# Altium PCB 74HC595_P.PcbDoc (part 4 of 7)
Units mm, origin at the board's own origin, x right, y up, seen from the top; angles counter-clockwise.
Board outline 89.11 x 89.03 mm, 2 copper layers (Top Layer, Bottom Layer); 552 components, 23 nets, 1488 pads, 408 vias.
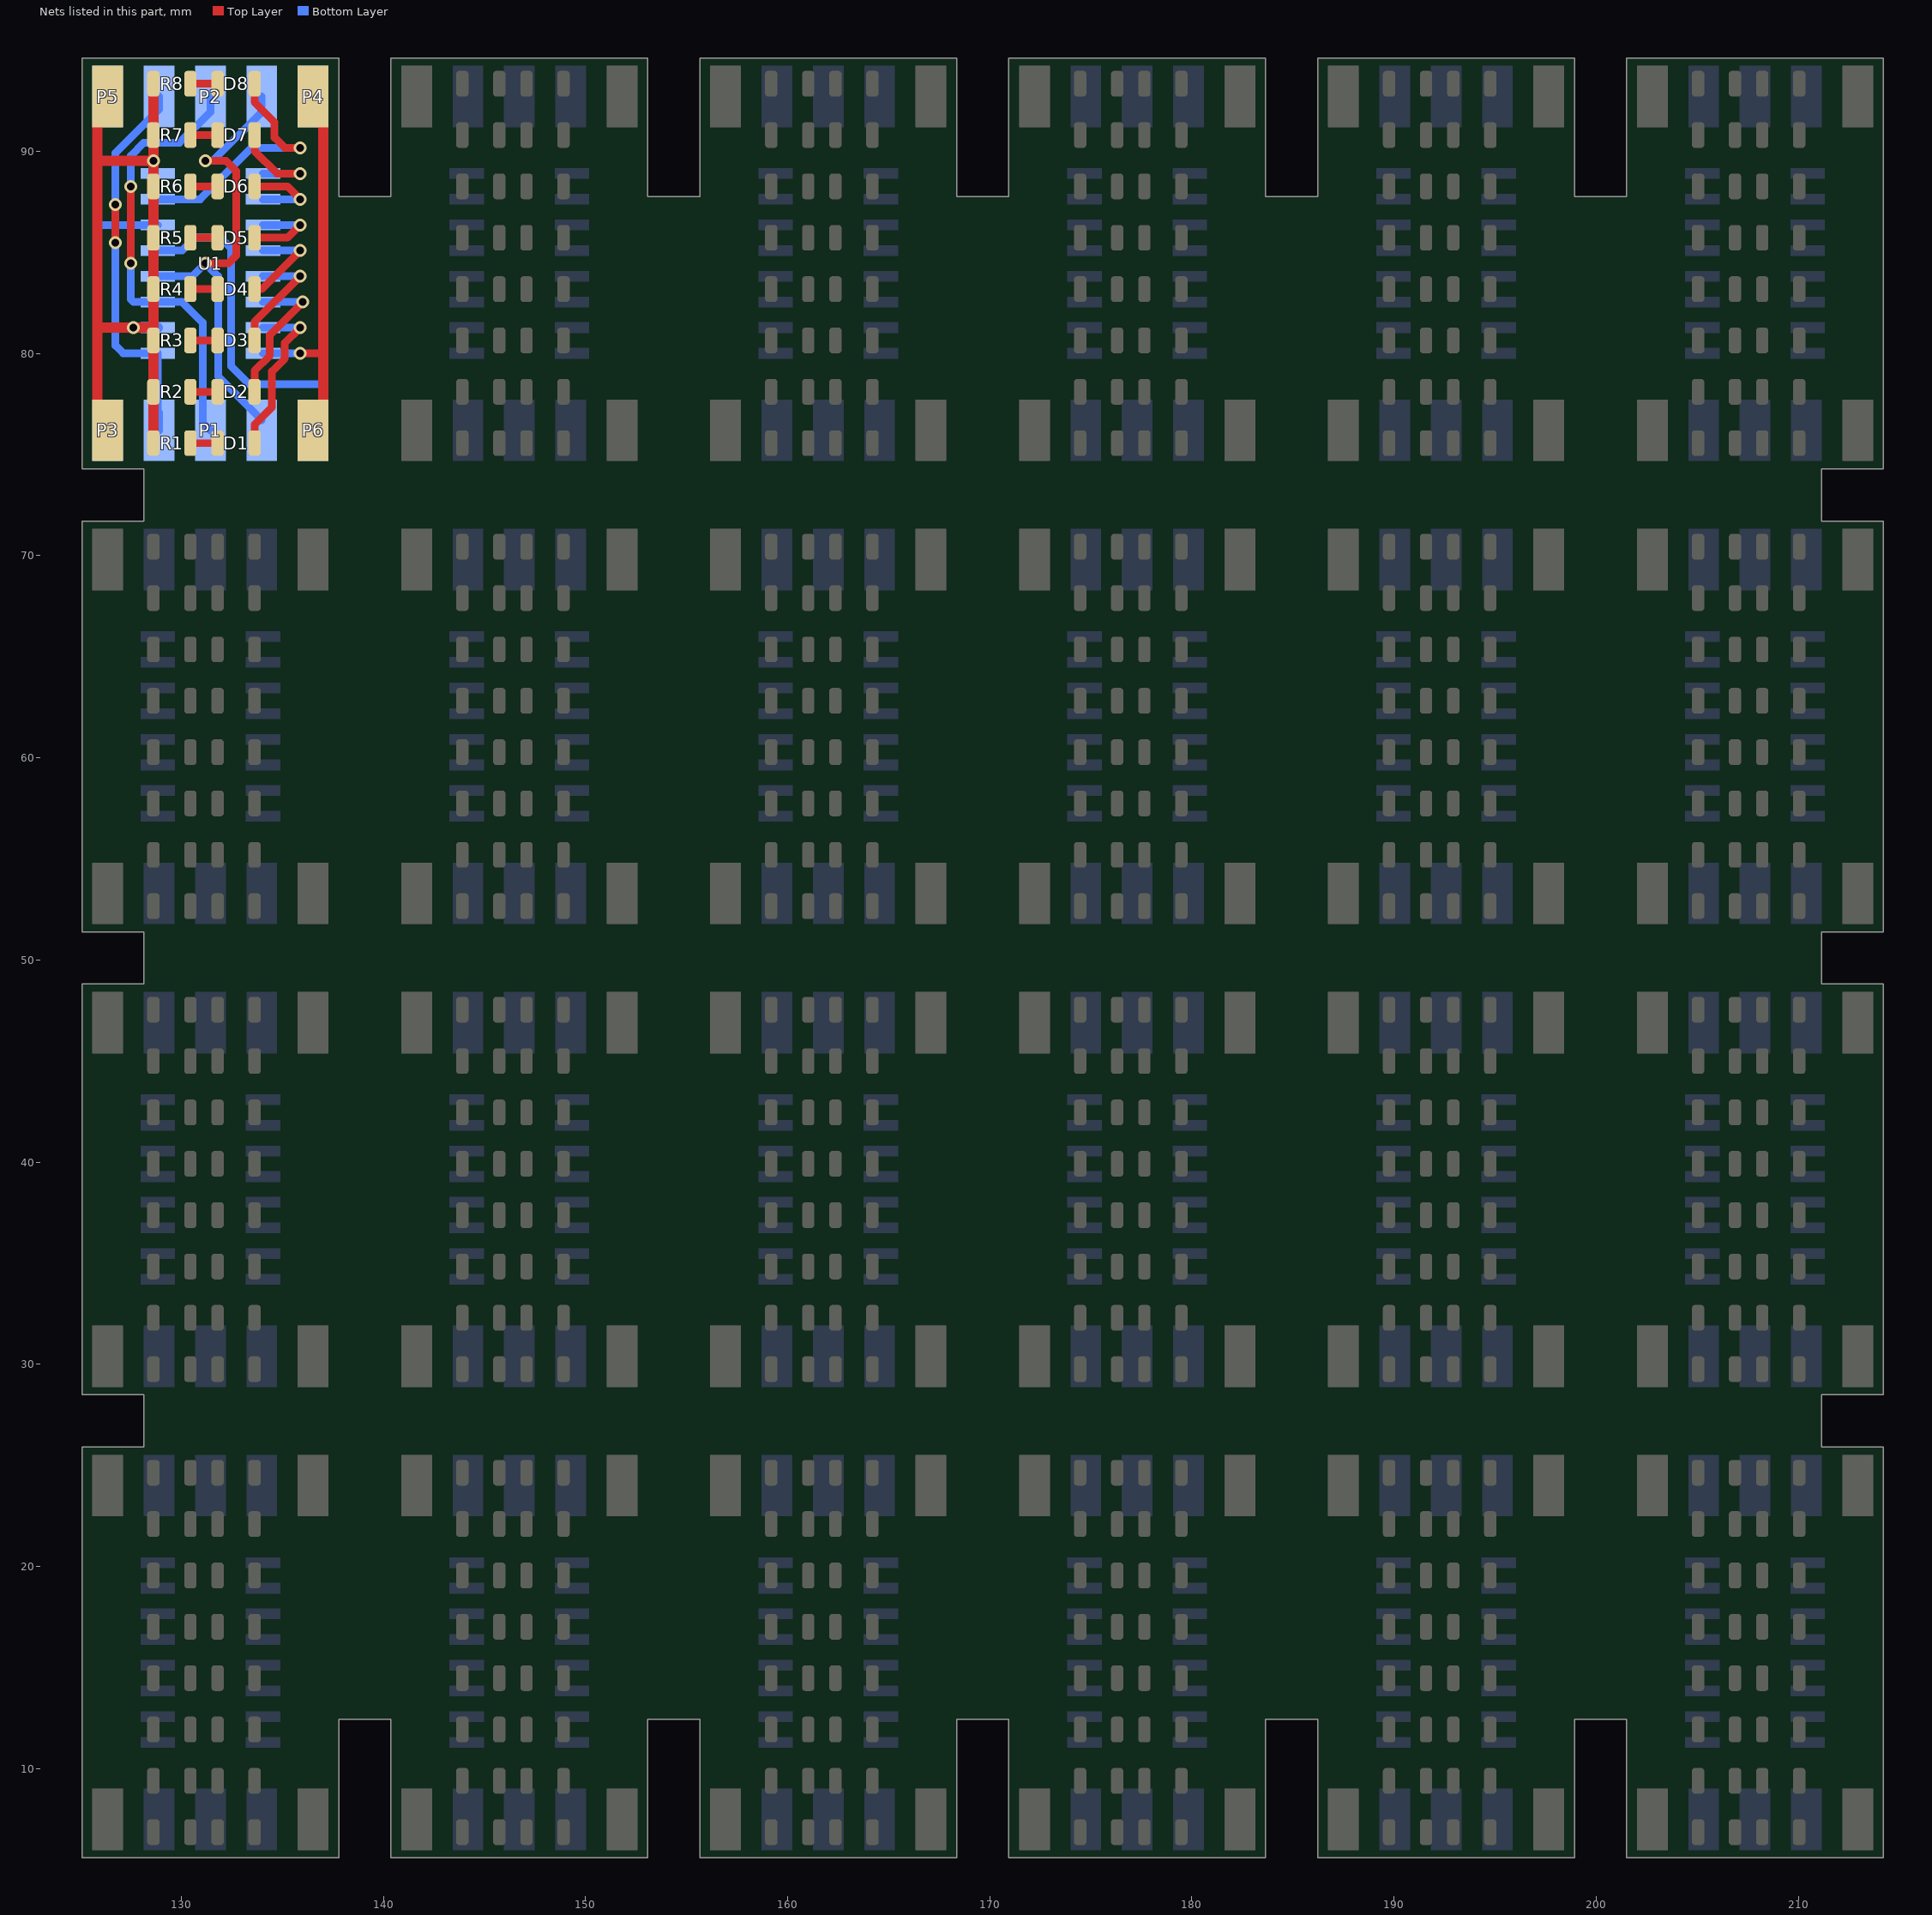
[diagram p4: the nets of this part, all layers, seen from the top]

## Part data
D1 D1_1 D1_1_1 D1_1_2 D1_1_3 D1_1_4 D1_2 D1_2_1 D1_2_1_1 D1_2_1_1_1 D1_2_1_1_2 D1_2_1_1_3 D1_2_1_1_4 D1_2_2 D1_2_2_1 D1_2_2_1_1 D1_2_2_1_2 D1_2_2_1_3 D1_2_2_1_4 D1_2_3 D1_2_3_1 D1_2_3_2 D1_2_3_3 D1_2_3_4 D2 D2_1 D2_1_1 D2_1_2 D2_1_3 D2_1_4 D2_2 D2_2_1 D2_2_1_1 D2_2_1_1_1 D2_2_1_1_2 D2_2_1_1_3 D2_2_1_1_4 D2_2_2 D2_2_2_1 D2_2_2_1_1 D2_2_2_1_2 D2_2_2_1_3 D2_2_2_1_4 D2_2_3 D2_2_3_1 D2_2_3_2 D2_2_3_3 D2_2_3_4 D3 D3_1 D3_1_1 D3_1_2 D3_1_3 D3_1_4 D3_2 D3_2_1 D3_2_1_1 D3_2_1_1_1 D3_2_1_1_2 D3_2_1_1_3 D3_2_1_1_4 D3_2_2 D3_2_2_1 D3_2_2_1_1 D3_2_2_1_2 D3_2_2_1_3 D3_2_2_1_4 D3_2_3 D3_2_3_1 D3_2_3_2 D3_2_3_3 D3_2_3_4 D4 D4_1 D4_1_1 D4_1_2 D4_1_3 D4_1_4 D4_2 D4_2_1 D4_2_1_1 D4_2_1_1_1 D4_2_1_1_2 D4_2_1_1_3 D4_2_1_1_4 D4_2_2 D4_2_2_1 D4_2_2_1_1 D4_2_2_1_2 D4_2_2_1_3 D4_2_2_1_4 D4_2_3 D4_2_3_1 D4_2_3_2 D4_2_3_3 D4_2_3_4 D5 D5_1 D5_1_1 D5_1_2 D5_1_3 D5_1_4 D5_2 D5_2_1 D5_2_1_1 D5_2_1_1_1 D5_2_1_1_2 D5_2_1_1_3 D5_2_1_1_4 D5_2_2 D5_2_2_1 D5_2_2_1_1 D5_2_2_1_2 D5_2_2_1_3 D5_2_2_1_4 D5_2_3 D5_2_3_1 D5_2_3_2 D5_2_3_3 D5_2_3_4 D6 D6_1 D6_1_1 D6_1_2 D6_1_3 D6_1_4 D6_2 D6_2_1 D6_2_1_1 D6_2_1_1_1 D6_2_1_1_2 D6_2_1_1_3 D6_2_1_1_4 D6_2_2 D6_2_2_1 D6_2_2_1_1 D6_2_2_1_2 D6_2_2_1_3 D6_2_2_1_4 D6_2_3 D6_2_3_1 D6_2_3_2 D6_2_3_3 D6_2_3_4 D7 D7_1 D7_1_1 D7_1_2 D7_1_3 D7_1_4 D7_2 D7_2_1 D7_2_1_1 D7_2_1_1_1 D7_2_1_1_2 D7_2_1_1_3 D7_2_1_1_4 D7_2_2 D7_2_2_1 D7_2_2_1_1 D7_2_2_1_2 D7_2_2_1_3 D7_2_2_1_4 D7_2_3 D7_2_3_1 D7_2_3_2 D7_2_3_3 D7_2_3_4 D8 D8_1 D8_1_1 D8_1_2 D8_1_3 D8_1_4 D8_2 D8_2_1 D8_2_1_1 D8_2_1_1_1 D8_2_1_1_2 D8_2_1_1_3 D8_2_1_1_4 D8_2_2 D8_2_2_1 D8_2_2_1_1 D8_2_2_1_2 D8_2_2_1_3 D8_2_2_1_4 D8_2_3 D8_2_3_1 D8_2_3_2 D8_2_3_3 D8_2_3_4: library part LED_0805, "LED"
P1 P1_1 P1_1_1 P1_1_2 P1_1_3 P1_1_4 P1_2 P1_2_1 P1_2_1_1 P1_2_1_1_1 P1_2_1_1_2 P1_2_1_1_3 P1_2_1_1_4 P1_2_2 P1_2_2_1 P1_2_2_1_1 P1_2_2_1_2 P1_2_2_1_3 P1_2_2_1_4 P1_2_3 P1_2_3_1 P1_2_3_2 P1_2_3_3 P1_2_3_4 P2 P2_1 P2_1_1 P2_1_2 P2_1_3 P2_1_4 P2_2 P2_2_1 P2_2_1_1 P2_2_1_1_1 P2_2_1_1_2 P2_2_1_1_3 P2_2_1_1_4 P2_2_2 P2_2_2_1 P2_2_2_1_1 P2_2_2_1_2 P2_2_2_1_3 P2_2_2_1_4 P2_2_3 P2_2_3_1 P2_2_3_2 P2_2_3_3 P2_2_3_4: "Header, 5-Pin"
P3 P3_1 P3_1_1 P3_1_2 P3_1_3 P3_1_4 P3_2 P3_2_1 P3_2_1_1 P3_2_1_1_1 P3_2_1_1_2 P3_2_1_1_3 P3_2_1_1_4 P3_2_2 P3_2_2_1 P3_2_2_1_1 P3_2_2_1_2 P3_2_2_1_3 P3_2_2_1_4 P3_2_3 P3_2_3_1 P3_2_3_2 P3_2_3_3 P3_2_3_4 P4 P4_1 P4_1_1 P4_1_2 P4_1_3 P4_1_4 P4_2 P4_2_1 P4_2_1_1 P4_2_1_1_1 P4_2_1_1_2 P4_2_1_1_3 P4_2_1_1_4 P4_2_2 P4_2_2_1 P4_2_2_1_1 P4_2_2_1_2 P4_2_2_1_3 P4_2_2_1_4 P4_2_3 P4_2_3_1 P4_2_3_2 P4_2_3_3 P4_2_3_4 P5 P5_1 P5_1_1 P5_1_2 P5_1_3 P5_1_4 P5_2 P5_2_1 P5_2_1_1 P5_2_1_1_1 P5_2_1_1_2 P5_2_1_1_3 P5_2_1_1_4 P5_2_2 P5_2_2_1 P5_2_2_1_1 P5_2_2_1_2 P5_2_2_1_3 P5_2_2_1_4 P5_2_3 P5_2_3_1 P5_2_3_2 P5_2_3_3 P5_2_3_4 P6 P6_1 P6_1_1 P6_1_2 P6_1_3 P6_1_4 P6_2 P6_2_1 P6_2_1_1 P6_2_1_1_1 P6_2_1_1_2 P6_2_1_1_3 P6_2_1_1_4 P6_2_2 P6_2_2_1 P6_2_2_1_1 P6_2_2_1_2 P6_2_2_1_3 P6_2_2_1_4 P6_2_3 P6_2_3_1 P6_2_3_2 P6_2_3_3 P6_2_3_4: "Header, 1-Pin"
R1 R1_1 R1_1_1 R1_1_2 R1_1_3 R1_1_4 R1_2 R1_2_1 R1_2_1_1 R1_2_1_1_1 R1_2_1_1_2 R1_2_1_1_3 R1_2_1_1_4 R1_2_2 R1_2_2_1 R1_2_2_1_1 R1_2_2_1_2 R1_2_2_1_3 R1_2_2_1_4 R1_2_3 R1_2_3_1 R1_2_3_2 R1_2_3_3 R1_2_3_4 R2 R2_1 R2_1_1 R2_1_2 R2_1_3 R2_1_4 R2_2 R2_2_1 R2_2_1_1 R2_2_1_1_1 R2_2_1_1_2 R2_2_1_1_3 R2_2_1_1_4 R2_2_2 R2_2_2_1 R2_2_2_1_1 R2_2_2_1_2 R2_2_2_1_3 R2_2_2_1_4 R2_2_3 R2_2_3_1 R2_2_3_2 R2_2_3_3 R2_2_3_4 R3 R3_1 R3_1_1 R3_1_2 R3_1_3 R3_1_4 R3_2 R3_2_1 R3_2_1_1 R3_2_1_1_1 R3_2_1_1_2 R3_2_1_1_3 R3_2_1_1_4 R3_2_2 R3_2_2_1 R3_2_2_1_1 R3_2_2_1_2 R3_2_2_1_3 R3_2_2_1_4 R3_2_3 R3_2_3_1 R3_2_3_2 R3_2_3_3 R3_2_3_4 R4 R4_1 R4_1_1 R4_1_2 R4_1_3 R4_1_4 R4_2 R4_2_1 R4_2_1_1 R4_2_1_1_1 R4_2_1_1_2 R4_2_1_1_3 R4_2_1_1_4 R4_2_2 R4_2_2_1 R4_2_2_1_1 R4_2_2_1_2 R4_2_2_1_3 R4_2_2_1_4 R4_2_3 R4_2_3_1 R4_2_3_2 R4_2_3_3 R4_2_3_4 R5 R5_1 R5_1_1 R5_1_2 R5_1_3 R5_1_4 R5_2 R5_2_1 R5_2_1_1 R5_2_1_1_1 R5_2_1_1_2 R5_2_1_1_3 R5_2_1_1_4 R5_2_2 R5_2_2_1 R5_2_2_1_1 R5_2_2_1_2 R5_2_2_1_3 R5_2_2_1_4 R5_2_3 R5_2_3_1 R5_2_3_2 R5_2_3_3 R5_2_3_4 R6 R6_1 R6_1_1 R6_1_2 R6_1_3 R6_1_4 R6_2 R6_2_1 R6_2_1_1 R6_2_1_1_1 R6_2_1_1_2 R6_2_1_1_3 R6_2_1_1_4 R6_2_2 R6_2_2_1 R6_2_2_1_1 R6_2_2_1_2 R6_2_2_1_3 R6_2_2_1_4 R6_2_3 R6_2_3_1 R6_2_3_2 R6_2_3_3 R6_2_3_4 R7 R7_1 R7_1_1 R7_1_2 R7_1_3 R7_1_4 R7_2 R7_2_1 R7_2_1_1 R7_2_1_1_1 R7_2_1_1_2 R7_2_1_1_3 R7_2_1_1_4 R7_2_2 R7_2_2_1 R7_2_2_1_1 R7_2_2_1_2 R7_2_2_1_3 R7_2_2_1_4 R7_2_3 R7_2_3_1 R7_2_3_2 R7_2_3_3 R7_2_3_4 R8 R8_1 R8_1_1 R8_1_2 R8_1_3 R8_1_4 R8_2 R8_2_1 R8_2_1_1 R8_2_1_1_1 R8_2_1_1_2 R8_2_1_1_3 R8_2_1_1_4 R8_2_2 R8_2_2_1 R8_2_2_1_1 R8_2_2_1_2 R8_2_2_1_3 R8_2_2_1_4 R8_2_3 R8_2_3_1 R8_2_3_2 R8_2_3_3 R8_2_3_4: library part Res_0805, "Resistor"
U1 U1_1 U1_1_1 U1_1_2 U1_1_3 U1_1_4 U1_2 U1_2_1 U1_2_1_1 U1_2_1_1_1 U1_2_1_1_2 U1_2_1_1_3 U1_2_1_1_4 U1_2_2 U1_2_2_1 U1_2_2_1_1 U1_2_2_1_2 U1_2_2_1_3 U1_2_2_1_4 U1_2_3 U1_2_3_1 U1_2_3_2 U1_2_3_3 U1_2_3_4: "No Description Available"

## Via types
v1: diameter 0.635, hole 0.381, Top Layer to Bottom Layer, 408 vias

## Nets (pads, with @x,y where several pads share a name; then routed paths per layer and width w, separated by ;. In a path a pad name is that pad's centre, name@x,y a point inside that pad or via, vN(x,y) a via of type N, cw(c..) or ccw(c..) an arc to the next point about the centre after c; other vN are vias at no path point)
BITOUT: P1.2 P2.2 U1.9 | length 20.1
  Top Layer w0.381: v1(126.746,85.471) v1(126.746,87.376)
  Bottom Layer w0.381: v1(126.746,85.471) 126.746,80.391 127.127,80.01 U1.9@128.841,80.01 P1.2@128.841,76.263 ; v1(126.746,87.376) 126.746,89.916 128.905,92.075 P2.2@128.905,92.71 ; P1.2@128.905,76.2 P1.2@128.905,77.089
BITSCLK: P1.3 P2.3 U1.11 | length 22.2
  Top Layer w0.381: v1(127.508,84.455) v1(127.508,88.265)
  Bottom Layer w0.381: v1(127.508,84.455) 127.508,82.677 127.635,82.55 U1.11@128.841,82.55 130.048,82.55 131.064,81.534 131.064,76.581 P1.3@131.445,76.2 ; v1(127.508,88.265) 127.508,89.78 128.152,90.424 129.921,90.424 131.445,91.948 P2.3@131.445,92.71
DATAINPUT: P1.1 P2.1 U1.14 | length 18.1
  Bottom Layer w0.381: P1.1@125.857,76.835 P2.1@125.857,92.075 ; 125.984,86.36 U1.14@128.841,86.36
GND: P4.1 P6.1 U1.8 | length 17
  Top Layer w0.381: v1(135.89,80.01) 137.033,80.01
  Top Layer w0.508: P6.1@137.033,77.47 137.033,80.01 P4.1@137.033,91.44
  Bottom Layer w0.381: U1.8@134.048,80.01 v1(135.89,80.01)
MEMSCLK: P1.4 P2.4 U1.12 | length 23.7
  Top Layer w0.381: v1(131.191,84.455) 132.334,84.455 132.715,84.836 132.715,89.027 132.207,89.535 v1(131.191,89.535)
  Bottom Layer w0.381: U1.12@128.841,83.82 130.556,83.82 v1(131.191,84.455) 131.826,83.82 131.826,78.867 P1.4@133.985,76.708 ; v1(131.191,89.535) 131.572,89.535 133.985,91.948 P2.4@133.985,92.71
NetD1_2: D1.2 R1.1 | length 1.3
  Top Layer w0.381: R1.1@130.454,75.565 D1.2@131.801,75.565
NetD2_2: D2.2 R2.1 | length 1.3
  Top Layer w0.381: R2.1@130.454,78.105 D2.2@131.801,78.105
NetD3_2: D3.2 R3.1 | length 1.3
  Top Layer w0.381: R3.1@130.454,80.645 D3.2@131.801,80.645
NetD4_2: D4.2 R4.1 | length 1.3
  Top Layer w0.381: R4.1@130.454,83.185 D4.2@131.801,83.185
NetD5_2: D5.2 R5.1 | length 1.3
  Top Layer w0.381: R5.1@130.454,85.725 D5.2@131.801,85.725
NetD6_2: D6.2 R6.1 | length 1.3
  Top Layer w0.381: R6.1@130.454,88.265 D6.2@131.801,88.265
NetD7_2: D7.2 R7.1 | length 1.3
  Top Layer w0.381: R7.1@130.454,90.805 D7.2@131.801,90.805
NetD8_2: D8.2 R8.1 | length 1.3
  Top Layer w0.381: R8.1@130.454,93.345 D8.2@131.801,93.345
OUTENABLE: P1.5 P2.5 U1.13 | length 30.1
  Bottom Layer w0.381: U1.13@128.841,85.09 130.048,85.09 130.683,85.725 131.953,85.725 132.461,85.217 132.461,79.375 133.35,78.486 137.033,78.486 ; P1.5@137.033,76.835 137.033,78.486 ; P2.5@137.033,92.075 137.033,78.486
Q0: D8.1 U1.15 | length 12.7
  Top Layer w0.381: D8.1@133.629,93.345 133.629,92.431 134.62,91.44 134.62,90.678 135.128,90.17 v1(135.89,90.17)
  Bottom Layer w0.381: U1.15@128.841,87.63 130.937,87.63 133.477,90.17 v1(135.89,90.17)
Q1: D7.1 U1.1 | length 5.6
  Top Layer w0.381: D7.1@133.629,90.591 D7.1@133.629,90.805 133.629,90.018 134.747,88.9 v1(135.89,88.9)
  Bottom Layer w0.381: U1.1@134.048,88.9 v1(135.89,88.9)
Q2: D6.1 U1.2 | length 4.4
  Top Layer w0.381: D6.1@133.629,88.265 135.255,88.265 v1(135.89,87.63)
  Bottom Layer w0.381: U1.2@134.048,87.63 v1(135.89,87.63)
Q3: D5.1 U1.3 | length 4.4
  Top Layer w0.381: D5.1@133.629,85.725 135.255,85.725 v1(135.89,86.36)
  Bottom Layer w0.381: U1.3@134.048,86.36 v1(135.89,86.36)
Q4: D4.1 U1.4 | length 5.2
  Top Layer w0.381: D4.1@133.629,83.464 D4.1@133.629,83.185 133.985,83.185 v1(135.89,85.09)
  Bottom Layer w0.381: U1.4@134.048,85.09 v1(135.89,85.09)
Q5: D3.1 U1.5 | length 6
  Top Layer w0.381: D3.1@133.629,80.645 133.629,81.559 v1(135.89,83.82)
  Bottom Layer w0.381: U1.5@134.048,83.82 v1(135.89,83.82)
Q6: D2.1 U1.6 | length 7.4
  Top Layer w0.381: D2.1@133.629,78.105 133.629,79.146 134.379,79.896 134.379,80.912 v1(136.017,82.55)
  Bottom Layer w0.381: U1.6@134.048,82.55 v1(136.017,82.55)
Q7: D1.1 U1.7 | length 8.5
  Top Layer w0.381: D1.1@133.629,75.565 133.629,76.479 134.493,77.343 134.493,79.112 135.128,79.747 135.128,80.518 v1(135.89,81.28)
  Bottom Layer w0.381: U1.7@134.048,81.28 v1(135.89,81.28)
VCC: P3.1 P5.1 R1.2 R2.2 R3.2 R4.2 R5.2 R6.2 R7.2 R8.2 U1.10 U1.16 | length 38.7
  Top Layer w0.508: P3.1@125.857,77.47 P5.1@125.857,91.44 ; 125.984,81.28 v1(127.635,81.28) 128.626,81.28 ; 125.984,89.535 v1(128.626,89.535) ; R1.2@128.626,75.565 R2.2@128.626,78.105 R3.2@128.626,80.645 R4.2@128.626,83.185 R5.2@128.626,85.725 R6.2@128.626,88.265 v1(128.626,89.535) ; R8.2@128.626,93.345 R7.2@128.626,90.805 v1(128.626,89.535)
  Bottom Layer w0.508: v1(127.635,81.28) U1.10@128.841,81.28 ; U1.16@128.626,89.116 v1(128.626,89.535)
pads on no net: D1_1.1 D1_1.2 D1_1_1.1 D1_1_1.2 D1_1_2.1 D1_1_2.2 D1_1_3.1 D1_1_3.2 D1_1_4.1 D1_1_4.2 D1_2.1 D1_2.2 D1_2_1.1 D1_2_1.2 D1_2_1_1.1 D1_2_1_1.2 D1_2_1_1_1.1 D1_2_1_1_1.2 D1_2_1_1_2.1 D1_2_1_1_2.2 D1_2_1_1_3.1 D1_2_1_1_3.2 D1_2_1_1_4.1 D1_2_1_1_4.2 D1_2_2.1 D1_2_2.2 D1_2_2_1.1 D1_2_2_1.2 D1_2_2_1_1.1 D1_2_2_1_1.2 D1_2_2_1_2.1 D1_2_2_1_2.2 D1_2_2_1_3.1 D1_2_2_1_3.2 D1_2_2_1_4.1 D1_2_2_1_4.2 D1_2_3.1 D1_2_3.2 D1_2_3_1.1 D1_2_3_1.2 D1_2_3_2.1 D1_2_3_2.2 D1_2_3_3.1 D1_2_3_3.2 D1_2_3_4.1 D1_2_3_4.2 D2_1.1 D2_1.2 D2_1_1.1 D2_1_1.2 D2_1_2.1 D2_1_2.2 D2_1_3.1 D2_1_3.2 D2_1_4.1 D2_1_4.2 D2_2.1 D2_2.2 D2_2_1.1 D2_2_1.2 D2_2_1_1.1 D2_2_1_1.2 D2_2_1_1_1.1 D2_2_1_1_1.2 D2_2_1_1_2.1 D2_2_1_1_2.2 D2_2_1_1_3.1 D2_2_1_1_3.2 D2_2_1_1_4.1 D2_2_1_1_4.2 D2_2_2.1 D2_2_2.2 D2_2_2_1.1 D2_2_2_1.2 D2_2_2_1_1.1 D2_2_2_1_1.2 D2_2_2_1_2.1 D2_2_2_1_2.2 D2_2_2_1_3.1 D2_2_2_1_3.2 D2_2_2_1_4.1 D2_2_2_1_4.2 D2_2_3.1 D2_2_3.2 D2_2_3_1.1 D2_2_3_1.2 D2_2_3_2.1 D2_2_3_2.2 D2_2_3_3.1 D2_2_3_3.2 D2_2_3_4.1 D2_2_3_4.2 D3_1.1 D3_1.2 D3_1_1.1 D3_1_1.2 D3_1_2.1 D3_1_2.2 D3_1_3.1 D3_1_3.2 D3_1_4.1 D3_1_4.2 D3_2.1 D3_2.2 D3_2_1.1 D3_2_1.2 D3_2_1_1.1 D3_2_1_1.2 D3_2_1_1_1.1 D3_2_1_1_1.2 D3_2_1_1_2.1 D3_2_1_1_2.2 D3_2_1_1_3.1 D3_2_1_1_3.2 D3_2_1_1_4.1 D3_2_1_1_4.2 D3_2_2.1 D3_2_2.2 D3_2_2_1.1 D3_2_2_1.2 D3_2_2_1_1.1 D3_2_2_1_1.2 D3_2_2_1_2.1 D3_2_2_1_2.2 D3_2_2_1_3.1 D3_2_2_1_3.2 D3_2_2_1_4.1 D3_2_2_1_4.2 D3_2_3.1 D3_2_3.2 D3_2_3_1.1 D3_2_3_1.2 D3_2_3_2.1 D3_2_3_2.2 D3_2_3_3.1 D3_2_3_3.2 D3_2_3_4.1 D3_2_3_4.2 D4_1.1 D4_1.2 D4_1_1.1 D4_1_1.2 D4_1_2.1 D4_1_2.2 D4_1_3.1 D4_1_3.2 D4_1_4.1 D4_1_4.2 D4_2.1 D4_2.2 D4_2_1.1 D4_2_1.2 D4_2_1_1.1 D4_2_1_1.2 D4_2_1_1_1.1 D4_2_1_1_1.2 D4_2_1_1_2.1 D4_2_1_1_2.2 D4_2_1_1_3.1 D4_2_1_1_3.2 D4_2_1_1_4.1 D4_2_1_1_4.2 D4_2_2.1 D4_2_2.2 D4_2_2_1.1 D4_2_2_1.2 D4_2_2_1_1.1 D4_2_2_1_1.2 D4_2_2_1_2.1 D4_2_2_1_2.2 D4_2_2_1_3.1 D4_2_2_1_3.2 D4_2_2_1_4.1 D4_2_2_1_4.2 D4_2_3.1 D4_2_3.2 D4_2_3_1.1 D4_2_3_1.2 D4_2_3_2.1 D4_2_3_2.2 D4_2_3_3.1 D4_2_3_3.2 D4_2_3_4.1 D4_2_3_4.2 D5_1.1 D5_1.2 D5_1_1.1 D5_1_1.2 D5_1_2.1 D5_1_2.2 D5_1_3.1 D5_1_3.2 D5_1_4.1 D5_1_4.2 D5_2.1 D5_2.2 D5_2_1.1 D5_2_1.2 D5_2_1_1.1 D5_2_1_1.2 D5_2_1_1_1.1 D5_2_1_1_1.2 D5_2_1_1_2.1 D5_2_1_1_2.2 D5_2_1_1_3.1 D5_2_1_1_3.2 D5_2_1_1_4.1 D5_2_1_1_4.2 D5_2_2.1 D5_2_2.2 D5_2_2_1.1 D5_2_2_1.2 D5_2_2_1_1.1 D5_2_2_1_1.2 D5_2_2_1_2.1 D5_2_2_1_2.2 D5_2_2_1_3.1 D5_2_2_1_3.2 D5_2_2_1_4.1 D5_2_2_1_4.2 D5_2_3.1 D5_2_3.2 D5_2_3_1.1 D5_2_3_1.2 D5_2_3_2.1 D5_2_3_2.2 D5_2_3_3.1 D5_2_3_3.2 D5_2_3_4.1 D5_2_3_4.2 D6_1.1 D6_1.2 D6_1_1.1 D6_1_1.2 D6_1_2.1 D6_1_2.2 D6_1_3.1 D6_1_3.2 D6_1_4.1 D6_1_4.2 D6_2.1 D6_2.2 D6_2_1.1 D6_2_1.2 D6_2_1_1.1 D6_2_1_1.2 D6_2_1_1_1.1 D6_2_1_1_1.2 D6_2_1_1_2.1 D6_2_1_1_2.2 D6_2_1_1_3.1 D6_2_1_1_3.2 D6_2_1_1_4.1 D6_2_1_1_4.2 D6_2_2.1 D6_2_2.2 D6_2_2_1.1 D6_2_2_1.2 D6_2_2_1_1.1 D6_2_2_1_1.2 D6_2_2_1_2.1 D6_2_2_1_2.2 D6_2_2_1_3.1 D6_2_2_1_3.2 D6_2_2_1_4.1 D6_2_2_1_4.2 D6_2_3.1 D6_2_3.2 D6_2_3_1.1 D6_2_3_1.2 D6_2_3_2.1 D6_2_3_2.2 D6_2_3_3.1 D6_2_3_3.2 D6_2_3_4.1 D6_2_3_4.2 D7_1.1 D7_1.2 D7_1_1.1 D7_1_1.2 D7_1_2.1 D7_1_2.2 D7_1_3.1 D7_1_3.2 D7_1_4.1 D7_1_4.2 D7_2.1 D7_2.2 D7_2_1.1 D7_2_1.2 D7_2_1_1.1 D7_2_1_1.2 D7_2_1_1_1.1 D7_2_1_1_1.2 D7_2_1_1_2.1 D7_2_1_1_2.2 D7_2_1_1_3.1 D7_2_1_1_3.2 D7_2_1_1_4.1 D7_2_1_1_4.2 D7_2_2.1 D7_2_2.2 D7_2_2_1.1 D7_2_2_1.2 D7_2_2_1_1.1 D7_2_2_1_1.2 D7_2_2_1_2.1 D7_2_2_1_2.2 D7_2_2_1_3.1 D7_2_2_1_3.2 D7_2_2_1_4.1 D7_2_2_1_4.2 D7_2_3.1 D7_2_3.2 D7_2_3_1.1 D7_2_3_1.2 D7_2_3_2.1 D7_2_3_2.2 D7_2_3_3.1 D7_2_3_3.2 D7_2_3_4.1 D7_2_3_4.2 D8_1.1 D8_1.2 D8_1_1.1 D8_1_1.2 D8_1_2.1 D8_1_2.2 D8_1_3.1 D8_1_3.2 D8_1_4.1 D8_1_4.2 D8_2.1 D8_2.2 D8_2_1.1 D8_2_1.2 D8_2_1_1.1 D8_2_1_1.2 D8_2_1_1_1.1 D8_2_1_1_1.2 D8_2_1_1_2.1 D8_2_1_1_2.2 D8_2_1_1_3.1 D8_2_1_1_3.2 D8_2_1_1_4.1 D8_2_1_1_4.2 D8_2_2.1 D8_2_2.2 D8_2_2_1.1 D8_2_2_1.2 D8_2_2_1_1.1 D8_2_2_1_1.2 D8_2_2_1_2.1 D8_2_2_1_2.2 D8_2_2_1_3.1 D8_2_2_1_3.2 D8_2_2_1_4.1 D8_2_2_1_4.2 D8_2_3.1 D8_2_3.2 D8_2_3_1.1 D8_2_3_1.2 D8_2_3_2.1 D8_2_3_2.2 D8_2_3_3.1 D8_2_3_3.2 D8_2_3_4.1 D8_2_3_4.2 P1_1.1 P1_1.2 P1_1.3 P1_1.4 P1_1.5 P1_1_1.1 P1_1_1.2 P1_1_1.3 P1_1_1.4 P1_1_1.5 P1_1_2.1 P1_1_2.2 P1_1_2.3 P1_1_2.4 P1_1_2.5 P1_1_3.1 P1_1_3.2 P1_1_3.3 P1_1_3.4 P1_1_3.5 P1_1_4.1 P1_1_4.2 P1_1_4.3 P1_1_4.4 P1_1_4.5 P1_2.1 P1_2.2 P1_2.3 P1_2.4 P1_2.5 P1_2_1.1 P1_2_1.2 P1_2_1.3 P1_2_1.4 P1_2_1.5 P1_2_1_1.1 P1_2_1_1.2 P1_2_1_1.3 P1_2_1_1.4 P1_2_1_1.5 P1_2_1_1_1.1 P1_2_1_1_1.2 P1_2_1_1_1.3 P1_2_1_1_1.4 P1_2_1_1_1.5 P1_2_1_1_2.1 P1_2_1_1_2.2 P1_2_1_1_2.3 P1_2_1_1_2.4 P1_2_1_1_2.5 P1_2_1_1_3.1 P1_2_1_1_3.2 P1_2_1_1_3.3 P1_2_1_1_3.4 P1_2_1_1_3.5 P1_2_1_1_4.1 P1_2_1_1_4.2 P1_2_1_1_4.3 P1_2_1_1_4.4 P1_2_1_1_4.5 P1_2_2.1 P1_2_2.2 P1_2_2.3 P1_2_2.4 P1_2_2.5 P1_2_2_1.1 P1_2_2_1.2 P1_2_2_1.3 P1_2_2_1.4 P1_2_2_1.5 P1_2_2_1_1.1 P1_2_2_1_1.2 P1_2_2_1_1.3 P1_2_2_1_1.4 P1_2_2_1_1.5 P1_2_2_1_2.1 P1_2_2_1_2.2 P1_2_2_1_2.3 P1_2_2_1_2.4 P1_2_2_1_2.5 P1_2_2_1_3.1 P1_2_2_1_3.2 P1_2_2_1_3.3 P1_2_2_1_3.4 P1_2_2_1_3.5 P1_2_2_1_4.1 P1_2_2_1_4.2 P1_2_2_1_4.3 P1_2_2_1_4.4 P1_2_2_1_4.5 P1_2_3.1 P1_2_3.2 P1_2_3.3 P1_2_3.4 P1_2_3.5 P1_2_3_1.1 P1_2_3_1.2 P1_2_3_1.3 P1_2_3_1.4 P1_2_3_1.5 P1_2_3_2.1 P1_2_3_2.2 P1_2_3_2.3 P1_2_3_2.4 P1_2_3_2.5 P1_2_3_3.1 P1_2_3_3.2 P1_2_3_3.3 P1_2_3_3.4 P1_2_3_3.5 P1_2_3_4.1 P1_2_3_4.2 P1_2_3_4.3 P1_2_3_4.4 P1_2_3_4.5 P2_1.1 P2_1.2 P2_1.3 P2_1.4 P2_1.5 P2_1_1.1 P2_1_1.2 P2_1_1.3 P2_1_1.4 P2_1_1.5 P2_1_2.1 P2_1_2.2 P2_1_2.3 P2_1_2.4 P2_1_2.5 P2_1_3.1 P2_1_3.2 P2_1_3.3 P2_1_3.4 P2_1_3.5 P2_1_4.1 P2_1_4.2 P2_1_4.3 P2_1_4.4 P2_1_4.5 P2_2.1 P2_2.2 P2_2.3 P2_2.4 P2_2.5 P2_2_1.1 P2_2_1.2 P2_2_1.3 P2_2_1.4 P2_2_1.5 P2_2_1_1.1 P2_2_1_1.2 P2_2_1_1.3 P2_2_1_1.4 P2_2_1_1.5 P2_2_1_1_1.1 P2_2_1_1_1.2 P2_2_1_1_1.3 P2_2_1_1_1.4 P2_2_1_1_1.5 P2_2_1_1_2.1 P2_2_1_1_2.2 P2_2_1_1_2.3 P2_2_1_1_2.4 P2_2_1_1_2.5 P2_2_1_1_3.1 P2_2_1_1_3.2 P2_2_1_1_3.3 P2_2_1_1_3.4 P2_2_1_1_3.5 P2_2_1_1_4.1 P2_2_1_1_4.2 P2_2_1_1_4.3 P2_2_1_1_4.4 P2_2_1_1_4.5 P2_2_2.1 P2_2_2.2 P2_2_2.3 P2_2_2.4 P2_2_2.5 P2_2_2_1.1 P2_2_2_1.2 P2_2_2_1.3 P2_2_2_1.4 P2_2_2_1.5 P2_2_2_1_1.1 P2_2_2_1_1.2 P2_2_2_1_1.3 P2_2_2_1_1.4 P2_2_2_1_1.5 P2_2_2_1_2.1 P2_2_2_1_2.2 P2_2_2_1_2.3 P2_2_2_1_2.4 P2_2_2_1_2.5 P2_2_2_1_3.1 P2_2_2_1_3.2 P2_2_2_1_3.3 P2_2_2_1_3.4 P2_2_2_1_3.5 P2_2_2_1_4.1 P2_2_2_1_4.2 P2_2_2_1_4.3 P2_2_2_1_4.4 P2_2_2_1_4.5 P2_2_3.1 P2_2_3.2 P2_2_3.3 P2_2_3.4 P2_2_3.5 P2_2_3_1.1 P2_2_3_1.2 P2_2_3_1.3 P2_2_3_1.4 P2_2_3_1.5 P2_2_3_2.1 P2_2_3_2.2 P2_2_3_2.3 P2_2_3_2.4 P2_2_3_2.5 P2_2_3_3.1 P2_2_3_3.2 P2_2_3_3.3 P2_2_3_3.4 P2_2_3_3.5 P2_2_3_4.1 P2_2_3_4.2 P2_2_3_4.3 P2_2_3_4.4 P2_2_3_4.5 P3_1.1 P3_1_1.1 P3_1_2.1 P3_1_3.1 P3_1_4.1 P3_2.1 P3_2_1.1 P3_2_1_1.1 P3_2_1_1_1.1 P3_2_1_1_2.1 P3_2_1_1_3.1 P3_2_1_1_4.1 P3_2_2.1 P3_2_2_1.1 P3_2_2_1_1.1 P3_2_2_1_2.1 P3_2_2_1_3.1 P3_2_2_1_4.1 P3_2_3.1 P3_2_3_1.1 P3_2_3_2.1 P3_2_3_3.1 P3_2_3_4.1 P4_1.1 P4_1_1.1 P4_1_2.1 P4_1_3.1 P4_1_4.1 P4_2.1 P4_2_1.1 P4_2_1_1.1 P4_2_1_1_1.1 P4_2_1_1_2.1 P4_2_1_1_3.1 P4_2_1_1_4.1 P4_2_2.1 P4_2_2_1.1 P4_2_2_1_1.1 P4_2_2_1_2.1 P4_2_2_1_3.1 P4_2_2_1_4.1 P4_2_3.1 P4_2_3_1.1 P4_2_3_2.1 P4_2_3_3.1 P4_2_3_4.1 P5_1.1 P5_1_1.1 P5_1_2.1 P5_1_3.1 P5_1_4.1 P5_2.1 P5_2_1.1 P5_2_1_1.1 P5_2_1_1_1.1 P5_2_1_1_2.1 P5_2_1_1_3.1 P5_2_1_1_4.1 P5_2_2.1 P5_2_2_1.1 P5_2_2_1_1.1 P5_2_2_1_2.1 P5_2_2_1_3.1 P5_2_2_1_4.1 P5_2_3.1 P5_2_3_1.1 P5_2_3_2.1 P5_2_3_3.1 P5_2_3_4.1 P6_1.1 P6_1_1.1 P6_1_2.1 P6_1_3.1 P6_1_4.1 P6_2.1 P6_2_1.1 P6_2_1_1.1 P6_2_1_1_1.1 P6_2_1_1_2.1 P6_2_1_1_3.1 P6_2_1_1_4.1 P6_2_2.1 P6_2_2_1.1 P6_2_2_1_1.1 P6_2_2_1_2.1 P6_2_2_1_3.1 P6_2_2_1_4.1 P6_2_3.1 P6_2_3_1.1 P6_2_3_2.1 P6_2_3_3.1 P6_2_3_4.1 R1_1.1 R1_1.2 R1_1_1.1 R1_1_1.2 R1_1_2.1 R1_1_2.2 R1_1_3.1 R1_1_3.2 R1_1_4.1 R1_1_4.2 R1_2.1 R1_2.2 R1_2_1.1 R1_2_1.2 R1_2_1_1.1 R1_2_1_1.2 R1_2_1_1_1.1 R1_2_1_1_1.2 R1_2_1_1_2.1 R1_2_1_1_2.2 R1_2_1_1_3.1 R1_2_1_1_3.2 R1_2_1_1_4.1 R1_2_1_1_4.2 R1_2_2.1 R1_2_2.2 R1_2_2_1.1 R1_2_2_1.2 R1_2_2_1_1.1 R1_2_2_1_1.2 R1_2_2_1_2.1 R1_2_2_1_2.2 R1_2_2_1_3.1 R1_2_2_1_3.2 R1_2_2_1_4.1 R1_2_2_1_4.2 R1_2_3.1 R1_2_3.2 R1_2_3_1.1 R1_2_3_1.2 R1_2_3_2.1 R1_2_3_2.2 R1_2_3_3.1 R1_2_3_3.2 R1_2_3_4.1 R1_2_3_4.2 R2_1.1 R2_1.2 R2_1_1.1 R2_1_1.2 R2_1_2.1 R2_1_2.2 R2_1_3.1 R2_1_3.2 R2_1_4.1 R2_1_4.2 R2_2.1 R2_2.2 R2_2_1.1 R2_2_1.2 R2_2_1_1.1 R2_2_1_1.2 R2_2_1_1_1.1 R2_2_1_1_1.2 R2_2_1_1_2.1 R2_2_1_1_2.2 R2_2_1_1_3.1 R2_2_1_1_3.2 R2_2_1_1_4.1 R2_2_1_1_4.2 R2_2_2.1 R2_2_2.2 R2_2_2_1.1 R2_2_2_1.2 R2_2_2_1_1.1 R2_2_2_1_1.2 R2_2_2_1_2.1 R2_2_2_1_2.2 R2_2_2_1_3.1 R2_2_2_1_3.2 R2_2_2_1_4.1 R2_2_2_1_4.2 R2_2_3.1 R2_2_3.2 R2_2_3_1.1 R2_2_3_1.2 R2_2_3_2.1 R2_2_3_2.2 R2_2_3_3.1 R2_2_3_3.2 R2_2_3_4.1 R2_2_3_4.2 R3_1.1 R3_1.2 R3_1_1.1 R3_1_1.2 R3_1_2.1 R3_1_2.2 R3_1_3.1 R3_1_3.2 R3_1_4.1 R3_1_4.2 R3_2.1 R3_2.2 R3_2_1.1 R3_2_1.2 R3_2_1_1.1 R3_2_1_1.2 R3_2_1_1_1.1 R3_2_1_1_1.2 R3_2_1_1_2.1 R3_2_1_1_2.2 R3_2_1_1_3.1 R3_2_1_1_3.2 R3_2_1_1_4.1 R3_2_1_1_4.2 R3_2_2.1 R3_2_2.2 R3_2_2_1.1 R3_2_2_1.2 R3_2_2_1_1.1 R3_2_2_1_1.2 R3_2_2_1_2.1 R3_2_2_1_2.2 R3_2_2_1_3.1 R3_2_2_1_3.2 R3_2_2_1_4.1 R3_2_2_1_4.2 R3_2_3.1 R3_2_3.2 R3_2_3_1.1 R3_2_3_1.2 R3_2_3_2.1 R3_2_3_2.2 R3_2_3_3.1 R3_2_3_3.2 R3_2_3_4.1 R3_2_3_4.2 R4_1.1 R4_1.2 R4_1_1.1 R4_1_1.2 R4_1_2.1 R4_1_2.2 R4_1_3.1 R4_1_3.2 R4_1_4.1 R4_1_4.2 R4_2.1 R4_2.2 R4_2_1.1 R4_2_1.2 R4_2_1_1.1 R4_2_1_1.2 R4_2_1_1_1.1 R4_2_1_1_1.2 R4_2_1_1_2.1 R4_2_1_1_2.2 R4_2_1_1_3.1 R4_2_1_1_3.2 R4_2_1_1_4.1 R4_2_1_1_4.2 R4_2_2.1 R4_2_2.2 R4_2_2_1.1 R4_2_2_1.2 R4_2_2_1_1.1 R4_2_2_1_1.2 R4_2_2_1_2.1 R4_2_2_1_2.2 R4_2_2_1_3.1 R4_2_2_1_3.2 R4_2_2_1_4.1 R4_2_2_1_4.2 R4_2_3.1 R4_2_3.2 R4_2_3_1.1 R4_2_3_1.2 R4_2_3_2.1 R4_2_3_2.2 R4_2_3_3.1 R4_2_3_3.2 R4_2_3_4.1 R4_2_3_4.2 R5_1.1 R5_1.2 R5_1_1.1 R5_1_1.2 R5_1_2.1 R5_1_2.2 R5_1_3.1 R5_1_3.2 R5_1_4.1 R5_1_4.2 R5_2.1 R5_2.2 R5_2_1.1 R5_2_1.2 R5_2_1_1.1 R5_2_1_1.2 R5_2_1_1_1.1 R5_2_1_1_1.2 R5_2_1_1_2.1 R5_2_1_1_2.2 R5_2_1_1_3.1 R5_2_1_1_3.2 R5_2_1_1_4.1 R5_2_1_1_4.2 R5_2_2.1 R5_2_2.2 R5_2_2_1.1 R5_2_2_1.2 R5_2_2_1_1.1 R5_2_2_1_1.2 R5_2_2_1_2.1 R5_2_2_1_2.2 R5_2_2_1_3.1 R5_2_2_1_3.2 R5_2_2_1_4.1 R5_2_2_1_4.2 R5_2_3.1 R5_2_3.2 R5_2_3_1.1 R5_2_3_1.2 R5_2_3_2.1 R5_2_3_2.2 R5_2_3_3.1 R5_2_3_3.2 R5_2_3_4.1 R5_2_3_4.2 R6_1.1 R6_1.2 R6_1_1.1 R6_1_1.2 R6_1_2.1 R6_1_2.2 R6_1_3.1 R6_1_3.2 R6_1_4.1 R6_1_4.2 R6_2.1 R6_2.2 R6_2_1.1 R6_2_1.2 R6_2_1_1.1 R6_2_1_1.2 R6_2_1_1_1.1 R6_2_1_1_1.2 R6_2_1_1_2.1 R6_2_1_1_2.2 R6_2_1_1_3.1 R6_2_1_1_3.2 R6_2_1_1_4.1 R6_2_1_1_4.2 R6_2_2.1 R6_2_2.2 R6_2_2_1.1 R6_2_2_1.2 R6_2_2_1_1.1 R6_2_2_1_1.2 R6_2_2_1_2.1 R6_2_2_1_2.2 R6_2_2_1_3.1 R6_2_2_1_3.2 R6_2_2_1_4.1 R6_2_2_1_4.2 R6_2_3.1 R6_2_3.2 R6_2_3_1.1 R6_2_3_1.2 R6_2_3_2.1 R6_2_3_2.2 R6_2_3_3.1 R6_2_3_3.2 R6_2_3_4.1 R6_2_3_4.2 R7_1.1 R7_1.2 R7_1_1.1 R7_1_1.2 R7_1_2.1 R7_1_2.2 R7_1_3.1 R7_1_3.2 R7_1_4.1 R7_1_4.2 R7_2.1 R7_2.2 R7_2_1.1 R7_2_1.2 R7_2_1_1.1 R7_2_1_1.2 R7_2_1_1_1.1 R7_2_1_1_1.2 R7_2_1_1_2.1 R7_2_1_1_2.2 R7_2_1_1_3.1 R7_2_1_1_3.2 R7_2_1_1_4.1 R7_2_1_1_4.2 R7_2_2.1 R7_2_2.2 R7_2_2_1.1 R7_2_2_1.2 R7_2_2_1_1.1 R7_2_2_1_1.2 R7_2_2_1_2.1 R7_2_2_1_2.2 R7_2_2_1_3.1 R7_2_2_1_3.2 R7_2_2_1_4.1 R7_2_2_1_4.2 R7_2_3.1 R7_2_3.2 R7_2_3_1.1 R7_2_3_1.2 R7_2_3_2.1 R7_2_3_2.2 R7_2_3_3.1 R7_2_3_3.2 R7_2_3_4.1 R7_2_3_4.2 R8_1.1 R8_1.2 R8_1_1.1 R8_1_1.2 R8_1_2.1 R8_1_2.2 R8_1_3.1 R8_1_3.2 R8_1_4.1 R8_1_4.2 R8_2.1 R8_2.2 R8_2_1.1 R8_2_1.2 R8_2_1_1.1 R8_2_1_1.2 R8_2_1_1_1.1 R8_2_1_1_1.2 R8_2_1_1_2.1 R8_2_1_1_2.2 R8_2_1_1_3.1 R8_2_1_1_3.2 R8_2_1_1_4.1 R8_2_1_1_4.2 R8_2_2.1 R8_2_2.2 R8_2_2_1.1 R8_2_2_1.2 R8_2_2_1_1.1 R8_2_2_1_1.2 R8_2_2_1_2.1 R8_2_2_1_2.2 R8_2_2_1_3.1 R8_2_2_1_3.2 R8_2_2_1_4.1 R8_2_2_1_4.2 R8_2_3.1 R8_2_3.2 R8_2_3_1.1 R8_2_3_1.2 R8_2_3_2.1 R8_2_3_2.2 R8_2_3_3.1 R8_2_3_3.2 R8_2_3_4.1 R8_2_3_4.2 U1_1.1 U1_1.2 U1_1.3 U1_1.4 U1_1.5 U1_1.6 U1_1.7 U1_1.8 U1_1.9 U1_1.10 U1_1.11 U1_1.12 U1_1.13 U1_1.14 U1_1.15 U1_1.16 U1_1_1.1 U1_1_1.2 U1_1_1.3 U1_1_1.4 U1_1_1.5 U1_1_1.6 U1_1_1.7 U1_1_1.8 U1_1_1.9 U1_1_1.10 U1_1_1.11 U1_1_1.12 U1_1_1.13 U1_1_1.14 U1_1_1.15 U1_1_1.16 U1_1_2.1 U1_1_2.2 U1_1_2.3 U1_1_2.4 U1_1_2.5 U1_1_2.6 U1_1_2.7 U1_1_2.8 U1_1_2.9 U1_1_2.10 U1_1_2.11 U1_1_2.12 U1_1_2.13 U1_1_2.14 U1_1_2.15 U1_1_2.16 U1_1_3.1 U1_1_3.2 U1_1_3.3 U1_1_3.4 U1_1_3.5 U1_1_3.6 U1_1_3.7 U1_1_3.8 U1_1_3.9 U1_1_3.10 U1_1_3.11 U1_1_3.12 U1_1_3.13 U1_1_3.14 U1_1_3.15 U1_1_3.16 U1_1_4.1 U1_1_4.2 U1_1_4.3 U1_1_4.4 U1_1_4.5 U1_1_4.6 U1_1_4.7 U1_1_4.8 U1_1_4.9 U1_1_4.10 U1_1_4.11 U1_1_4.12 U1_1_4.13 U1_1_4.14 U1_1_4.15 U1_1_4.16 U1_2.1 U1_2.2 U1_2.3 U1_2.4 U1_2.5 U1_2.6 U1_2.7 U1_2.8 U1_2.9 U1_2.10 U1_2.11 U1_2.12 U1_2.13 U1_2.14 U1_2.15 U1_2.16 U1_2_1.1 U1_2_1.2 U1_2_1.3 U1_2_1.4 U1_2_1.5 U1_2_1.6 U1_2_1.7 U1_2_1.8 U1_2_1.9 U1_2_1.10 U1_2_1.11 U1_2_1.12 U1_2_1.13 U1_2_1.14 U1_2_1.15 U1_2_1.16 U1_2_1_1.1 U1_2_1_1.2 U1_2_1_1.3 U1_2_1_1.4 U1_2_1_1.5 U1_2_1_1.6 U1_2_1_1.7 U1_2_1_1.8 U1_2_1_1.9 U1_2_1_1.10 U1_2_1_1.11 U1_2_1_1.12 U1_2_1_1.13 U1_2_1_1.14 U1_2_1_1.15 U1_2_1_1.16 U1_2_1_1_1.1 U1_2_1_1_1.2 U1_2_1_1_1.3 U1_2_1_1_1.4 U1_2_1_1_1.5 U1_2_1_1_1.6 U1_2_1_1_1.7 U1_2_1_1_1.8 U1_2_1_1_1.9 U1_2_1_1_1.10 U1_2_1_1_1.11 U1_2_1_1_1.12 U1_2_1_1_1.13 U1_2_1_1_1.14 U1_2_1_1_1.15 U1_2_1_1_1.16 U1_2_1_1_2.1 U1_2_1_1_2.2 U1_2_1_1_2.3 U1_2_1_1_2.4 U1_2_1_1_2.5 U1_2_1_1_2.6 U1_2_1_1_2.7 U1_2_1_1_2.8 U1_2_1_1_2.9 U1_2_1_1_2.10 U1_2_1_1_2.11 U1_2_1_1_2.12 U1_2_1_1_2.13 U1_2_1_1_2.14 U1_2_1_1_2.15 U1_2_1_1_2.16 U1_2_1_1_3.1 U1_2_1_1_3.2 U1_2_1_1_3.3 U1_2_1_1_3.4 U1_2_1_1_3.5 U1_2_1_1_3.6 U1_2_1_1_3.7 U1_2_1_1_3.8 U1_2_1_1_3.9 U1_2_1_1_3.10 U1_2_1_1_3.11 U1_2_1_1_3.12 U1_2_1_1_3.13 U1_2_1_1_3.14 U1_2_1_1_3.15 U1_2_1_1_3.16 U1_2_1_1_4.1 U1_2_1_1_4.2 U1_2_1_1_4.3 U1_2_1_1_4.4 U1_2_1_1_4.5 U1_2_1_1_4.6 U1_2_1_1_4.7 U1_2_1_1_4.8 U1_2_1_1_4.9 U1_2_1_1_4.10 U1_2_1_1_4.11 U1_2_1_1_4.12 U1_2_1_1_4.13 U1_2_1_1_4.14 U1_2_1_1_4.15 U1_2_1_1_4.16 U1_2_2.1 U1_2_2.2 U1_2_2.3 U1_2_2.4 U1_2_2.5 U1_2_2.6 U1_2_2.7 U1_2_2.8 U1_2_2.9 U1_2_2.10 U1_2_2.11 U1_2_2.12 U1_2_2.13 U1_2_2.14 U1_2_2.15 U1_2_2.16 U1_2_2_1.1 U1_2_2_1.2 U1_2_2_1.3 U1_2_2_1.4 U1_2_2_1.5 U1_2_2_1.6 U1_2_2_1.7 U1_2_2_1.8 U1_2_2_1.9 U1_2_2_1.10 U1_2_2_1.11 U1_2_2_1.12 U1_2_2_1.13 U1_2_2_1.14 U1_2_2_1.15 U1_2_2_1.16 U1_2_2_1_1.1 U1_2_2_1_1.2 U1_2_2_1_1.3 U1_2_2_1_1.4 U1_2_2_1_1.5 U1_2_2_1_1.6 U1_2_2_1_1.7 U1_2_2_1_1.8 U1_2_2_1_1.9 U1_2_2_1_1.10 U1_2_2_1_1.11 U1_2_2_1_1.12 U1_2_2_1_1.13 U1_2_2_1_1.14 U1_2_2_1_1.15 U1_2_2_1_1.16 U1_2_2_1_2.1 U1_2_2_1_2.2 U1_2_2_1_2.3 U1_2_2_1_2.4 U1_2_2_1_2.5 U1_2_2_1_2.6 U1_2_2_1_2.7 U1_2_2_1_2.8 U1_2_2_1_2.9 U1_2_2_1_2.10 U1_2_2_1_2.11 U1_2_2_1_2.12 U1_2_2_1_2.13 U1_2_2_1_2.14 U1_2_2_1_2.15 U1_2_2_1_2.16 U1_2_2_1_3.1 U1_2_2_1_3.2 U1_2_2_1_3.3 U1_2_2_1_3.4 U1_2_2_1_3.5 U1_2_2_1_3.6 U1_2_2_1_3.7 U1_2_2_1_3.8 U1_2_2_1_3.9 U1_2_2_1_3.10 U1_2_2_1_3.11 U1_2_2_1_3.12 U1_2_2_1_3.13 U1_2_2_1_3.14 U1_2_2_1_3.15 U1_2_2_1_3.16 U1_2_2_1_4.1 U1_2_2_1_4.2 U1_2_2_1_4.3 U1_2_2_1_4.4 U1_2_2_1_4.5 U1_2_2_1_4.6 U1_2_2_1_4.7 U1_2_2_1_4.8 U1_2_2_1_4.9 U1_2_2_1_4.10 U1_2_2_1_4.11 U1_2_2_1_4.12 U1_2_2_1_4.13 U1_2_2_1_4.14 U1_2_2_1_4.15 U1_2_2_1_4.16 U1_2_3.1 U1_2_3.2 U1_2_3.3 U1_2_3.4 U1_2_3.5 U1_2_3.6 U1_2_3.7 U1_2_3.8 U1_2_3.9 U1_2_3.10 U1_2_3.11 U1_2_3.12 U1_2_3.13 U1_2_3.14 U1_2_3.15 U1_2_3.16 U1_2_3_1.1 U1_2_3_1.2 U1_2_3_1.3 U1_2_3_1.4 U1_2_3_1.5 U1_2_3_1.6 U1_2_3_1.7 U1_2_3_1.8 U1_2_3_1.9 U1_2_3_1.10 U1_2_3_1.11 U1_2_3_1.12 U1_2_3_1.13 U1_2_3_1.14 U1_2_3_1.15 U1_2_3_1.16 U1_2_3_2.1 U1_2_3_2.2 U1_2_3_2.3 U1_2_3_2.4 U1_2_3_2.5 U1_2_3_2.6 U1_2_3_2.7 U1_2_3_2.8 U1_2_3_2.9 U1_2_3_2.10 U1_2_3_2.11 U1_2_3_2.12 U1_2_3_2.13 U1_2_3_2.14 U1_2_3_2.15 U1_2_3_2.16 U1_2_3_3.1 U1_2_3_3.2 U1_2_3_3.3 U1_2_3_3.4 U1_2_3_3.5 U1_2_3_3.6 U1_2_3_3.7 U1_2_3_3.8 U1_2_3_3.9 U1_2_3_3.10 U1_2_3_3.11 U1_2_3_3.12 U1_2_3_3.13 U1_2_3_3.14 U1_2_3_3.15 U1_2_3_3.16 U1_2_3_4.1 U1_2_3_4.2 U1_2_3_4.3 U1_2_3_4.4 U1_2_3_4.5 U1_2_3_4.6 U1_2_3_4.7 U1_2_3_4.8 U1_2_3_4.9 U1_2_3_4.10 U1_2_3_4.11 U1_2_3_4.12 U1_2_3_4.13 U1_2_3_4.14 U1_2_3_4.15 U1_2_3_4.16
